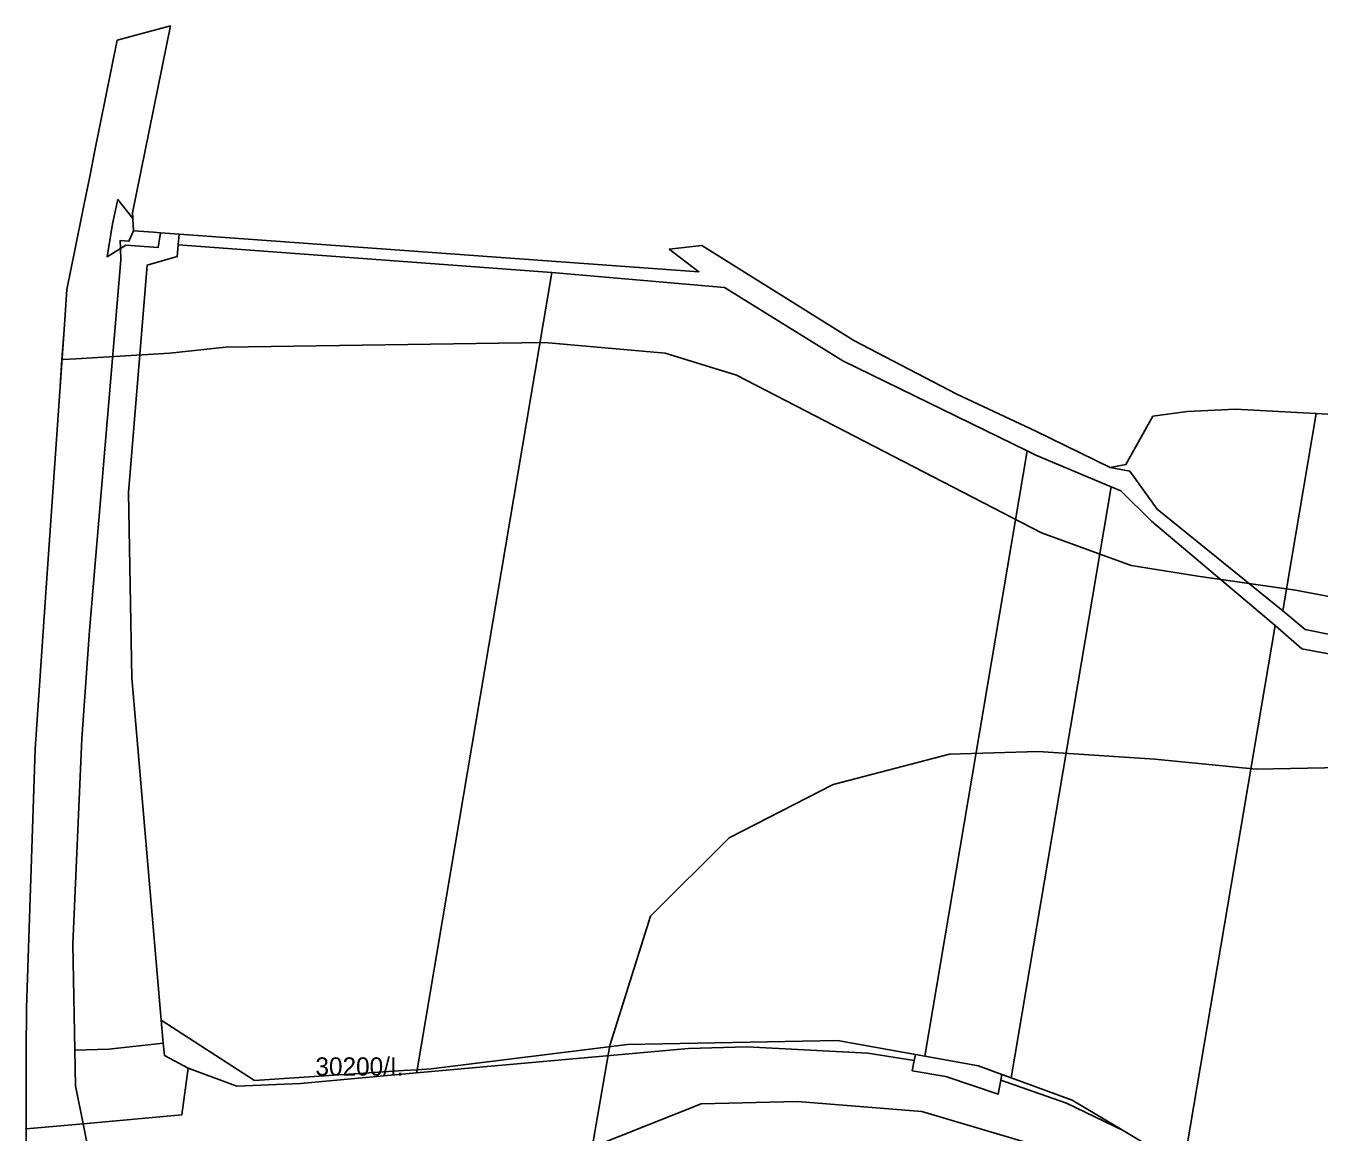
# Model space of a CAD drawing. Extents: x -545779 to -541342, y -1153413 to -1149956.
# Drawn here: x -545423.3 to -545068.2, y -1151257.3 to -1150953.6 of the extents above; entities that cross this region are included whole.
import ezdxf

# ---------------------------------------------------------------- set-up
doc = ezdxf.new("R2010")
doc.units = 0
for name, color, linetype in [('95560013', 7, 'Continuous'), ('95640013', 7, 'Continuous'), ('95660013', 7, 'Continuous')]:
    doc.layers.add(name, color=color, linetype=linetype)

msp = doc.modelspace()

# ---------------------------------------------------------------- linework, layer by layer
at = {"layer": '95560013'}
for points in [[(-545297.39, -1151130.75), (-545315.9, -1151240.2), (-545319.66, -1151240.45), (-545360.56, -1151243.15), (-545386.12, -1151226.6), (-545394.16, -1151132.63), (-545395.14, -1151081.73), (-545389.96, -1151019.3), (-545381.74, -1151016.95), (-545381.48, -1151013.76), (-545278.89, -1151021.33)], [(-545278.89, -1151021.33), (-545231.5, -1151025.48), (-545198.95, -1151045.58), (-545148.35, -1151070.32), (-545176.45, -1151236.52), (-545179.04, -1151236.05), (-545200.41, -1151232.2), (-545258.15, -1151233.28), (-545312, -1151239.94), (-545315.9, -1151240.2), (-545297.39, -1151130.75)], [(-544982.63, -1151074.88), (-544977.9, -1151041.47), (-544960.56, -1151045.47), (-544976.48, -1151139.6), (-544994.76, -1151135.53), (-545056.7, -1151122.48), (-545072.03, -1151119.36), (-545078.16, -1151114.22), (-545069, -1151060.1), (-545058.21, -1151060.69), (-545045.58, -1151063.06), (-544986.53, -1151074.15)], [(-545069, -1151060.1), (-545078.16, -1151114.22), (-545112.66, -1151086.29), (-545120.22, -1151075.9), (-545125.62, -1151074.91), (-545121.27, -1151074.07), (-545113.86, -1151060.79), (-545104.44, -1151059.55), (-545091.15, -1151058.89), (-545072.64, -1151059.9)], [(-545155.29, -1151241.53), (-545161.75, -1151239.16), (-545176.45, -1151236.52), (-545148.35, -1151070.32), (-545146.03, -1151071.46), (-545125.33, -1151080.16), (-545152.78, -1151242.45)], [(-545105.44, -1151266.77), (-545111.01, -1151263.46), (-545122.03, -1151256.92), (-545136.05, -1151248.6), (-545152.78, -1151242.45), (-545125.33, -1151080.16), (-545122.66, -1151081.28), (-545114.24, -1151089.6), (-545080.32, -1151118.3)], [(-545105.44, -1151266.77), (-545080.32, -1151118.3), (-545073, -1151124.65), (-545057.67, -1151127.49), (-544996.34, -1151140.83), (-544980.98, -1151144.11), (-544998.72, -1151249.04), (-545016.45, -1151353.98), (-545028.49, -1151339.4), (-545040.16, -1151326.96), (-545069.42, -1151294.93), (-545087.51, -1151280.35), (-545101.41, -1151269.18)], [(-545385.56, -1151232.93), (-545386.12, -1151226.6), (-545360.56, -1151243.15), (-545319.66, -1151240.45), (-545315.9, -1151240.2), (-545316.03, -1151241.06), (-545347.88, -1151243.99), (-545365.38, -1151244.69), (-545378.76, -1151239.82), (-545385.27, -1151236.27)], [(-545192.14, -1151235.65), (-545225.39, -1151233.96), (-545241.37, -1151234.37), (-545316.03, -1151241.06), (-545315.9, -1151240.2), (-545312, -1151239.94), (-545258.15, -1151233.28), (-545200.41, -1151232.2), (-545179.04, -1151236.05), (-545179.36, -1151237.66)], [(-545137.57, -1151249.39), (-545155.59, -1151243.1), (-545155.29, -1151241.53), (-545152.78, -1151242.45), (-545136.05, -1151248.6), (-545122.03, -1151256.92)]]:
    msp.add_lwpolyline(points, close=True, dxfattribs=at)
at = {"layer": '95640013'}
for points in [[(-545398.19, -1150957.61), (-545396.52, -1150957.15), (-545391.05, -1150955.66), (-545386.99, -1150954.56), (-545383.62, -1150953.64), (-545394.02, -1151005.01), (-545393.95, -1151006.48), (-545398.07, -1151001.33), (-545399.5, -1151008.02), (-545400.99, -1151017.04), (-545397.36, -1151014.79), (-545397.24, -1151017.86), (-545405.82, -1151119.6), (-545405.91, -1151120.92), (-545407.89, -1151149.38), (-545410.43, -1151205.78), (-545409.87, -1151234.83), (-545409.68, -1151244.6), (-545407.59, -1151255.04), (-545423.26, -1151256.45), (-545423.26, -1151254.63), (-545423.19, -1151235.41), (-545423.15, -1151223.23), (-545420.74, -1151152.25), (-545417.78, -1151109.17), (-545413.99, -1151053.99), (-545412.82, -1151037.01), (-545412.63, -1151034.32), (-545412.06, -1151026.02), (-545409.87, -1151015.21), (-545407.57, -1151003.88), (-545405.67, -1150994.5), (-545404.42, -1150988.32)], [(-545399.5, -1151008.02), (-545398.07, -1151001.33), (-545393.95, -1151006.48), (-545393.77, -1151009.92), (-545395.01, -1151012.76), (-545397.44, -1151012.59), (-545397.36, -1151014.79), (-545400.99, -1151017.04)], [(-545397.36, -1151014.79), (-545395.82, -1151013.84), (-545387, -1151014.5), (-545386.29, -1151010.46), (-545381.24, -1151010.83), (-545381.48, -1151013.76), (-545381.74, -1151016.95), (-545389.96, -1151019.3), (-545395.14, -1151081.73), (-545394.16, -1151132.63), (-545386.12, -1151226.6), (-545385.56, -1151232.93), (-545400.51, -1151234.57), (-545409.87, -1151234.83), (-545410.43, -1151205.78), (-545407.89, -1151149.38), (-545405.91, -1151120.92), (-545405.82, -1151119.6), (-545397.24, -1151017.86)], [(-545397.36, -1151014.79), (-545397.44, -1151012.59), (-545395.01, -1151012.76), (-545393.77, -1151009.92), (-545388.26, -1151010.32), (-545386.29, -1151010.46), (-545387, -1151014.5), (-545395.82, -1151013.84)], [(-545409.68, -1151244.6), (-545409.87, -1151234.83), (-545400.51, -1151234.57), (-545385.56, -1151232.93), (-545385.27, -1151236.27), (-545378.76, -1151239.82), (-545380.52, -1151252.6), (-545407.59, -1151255.04)], [(-545155.29, -1151241.53), (-545155.59, -1151243.1), (-545156.32, -1151246.89), (-545170.7, -1151242.07), (-545179.94, -1151240.55), (-545179.36, -1151237.66), (-545179.04, -1151236.05), (-545176.45, -1151236.52), (-545161.75, -1151239.16)], [(-545405.56, -1151265.22), (-545423.3, -1151266.92), (-545423.26, -1151256.45), (-545407.59, -1151255.04)]]:
    msp.add_lwpolyline(points, close=True, dxfattribs=at)
for points in [[(-545057.67, -1151127.49), (-545073, -1151124.65), (-545080.32, -1151118.3), (-545114.24, -1151089.6), (-545122.66, -1151081.28), (-545125.33, -1151080.16), (-545146.03, -1151071.46), (-545148.35, -1151070.32), (-545198.95, -1151045.58), (-545231.5, -1151025.48), (-545278.89, -1151021.33), (-545381.48, -1151013.76), (-545381.24, -1151010.83), (-545238.51, -1151021.15), (-545246.64, -1151014.94), (-545237.67, -1151013.97), (-545195.97, -1151040.02), (-545167.69, -1151054.76), (-545146.01, -1151064.93), (-545125.62, -1151074.91), (-545120.22, -1151075.9), (-545112.66, -1151086.29), (-545078.16, -1151114.22), (-545072.03, -1151119.36), (-545056.7, -1151122.48)], [(-545405.56, -1151265.22), (-545407.59, -1151255.04), (-545380.52, -1151252.6), (-545378.76, -1151239.82), (-545365.38, -1151244.69), (-545347.88, -1151243.99), (-545316.03, -1151241.06), (-545241.37, -1151234.37), (-545225.39, -1151233.96), (-545192.14, -1151235.65), (-545179.36, -1151237.66), (-545179.94, -1151240.55), (-545170.7, -1151242.07), (-545156.32, -1151246.89), (-545155.59, -1151243.1), (-545137.57, -1151249.39), (-545122.03, -1151256.92), (-545111.01, -1151263.46)]]:
    msp.add_lwpolyline(points, dxfattribs=at)
at = {"layer": '95660013'}
for points in [[(-545033.936, -1151116.231), (-545074.748, -1151108.579), (-545101.533, -1151104.753), (-545119.811, -1151101.778), (-545144.469, -1151092.85), (-545228.219, -1151049.487), (-545247.776, -1151043.536), (-545280.936, -1151040.56), (-545368.511, -1151041.835), (-545383.816, -1151043.536), (-545409.56, -1151045.031), (-545412.998, -1151045.231), (-545413.014, -1151045.232), (-545413.383, -1151045.253), (-545412.82, -1151037.01), (-545412.63, -1151034.32), (-545412.06, -1151026.02), (-545409.87, -1151015.21), (-545407.57, -1151003.88), (-545405.67, -1150994.5), (-545404.42, -1150988.32), (-545398.19, -1150957.61), (-545396.52, -1150957.15), (-545391.05, -1150955.66), (-545386.99, -1150954.56), (-545383.62, -1150953.64), (-545394.02, -1151005.01), (-545393.95, -1151006.48), (-545393.77, -1151009.92), (-545388.26, -1151010.32), (-545386.29, -1151010.46), (-545381.24, -1151010.83), (-545238.51, -1151021.15), (-545246.64, -1151014.94), (-545237.67, -1151013.97), (-545195.97, -1151040.02), (-545167.69, -1151054.76), (-545146.01, -1151064.93), (-545125.62, -1151074.91), (-545121.27, -1151074.07), (-545113.86, -1151060.79), (-545104.44, -1151059.55), (-545091.15, -1151058.89), (-545072.64, -1151059.9), (-545069, -1151060.1), (-545058.21, -1151060.69)], [(-545423.3, -1151266.92), (-545423.26, -1151256.45), (-545423.26, -1151254.63), (-545423.19, -1151235.41), (-545423.15, -1151223.23), (-545420.74, -1151152.25), (-545417.78, -1151109.17), (-545413.99, -1151053.99), (-545413.383, -1151045.253), (-545413.014, -1151045.232), (-545412.998, -1151045.231), (-545409.56, -1151045.031), (-545383.816, -1151043.536), (-545368.511, -1151041.835), (-545280.936, -1151040.56), (-545247.776, -1151043.536), (-545228.219, -1151049.487), (-545144.469, -1151092.85), (-545119.811, -1151101.778), (-545101.533, -1151104.753), (-545074.748, -1151108.579), (-545033.936, -1151116.231)], [(-545067.132, -1151310.344), (-545088.243, -1151295.525), (-545122.346, -1151276.734), (-545146.706, -1151260.726), (-545177.329, -1151251.678), (-545211.432, -1151248.895), (-545237.879, -1151249.591), (-545267.807, -1151261.422), (-545262.934, -1151233.583), (-545251.798, -1151198.088), (-545230.224, -1151176.512), (-545201.689, -1151161.897), (-545169.673, -1151153.545), (-545145.314, -1151152.849), (-545113.298, -1151154.937), (-545085.46, -1151157.721), (-545062.028, -1151157.228)], [(-545062.028, -1151157.228), (-545085.46, -1151157.721), (-545113.298, -1151154.937), (-545145.314, -1151152.849), (-545169.673, -1151153.545), (-545201.689, -1151161.897), (-545230.224, -1151176.512), (-545251.798, -1151198.088), (-545262.934, -1151233.583), (-545267.807, -1151261.422)], [(-545267.807, -1151261.422), (-545237.879, -1151249.591), (-545211.432, -1151248.895), (-545177.329, -1151251.678), (-545146.706, -1151260.726)]]:
    msp.add_lwpolyline(points, dxfattribs=at)

# ---------------------------------------------------------------- texts
msp.add_text('30200/I.', height=5, rotation=0, dxfattribs=at).set_placement((-545343.794, -1151241.816))

doc.saveas('drawing.dxf')
